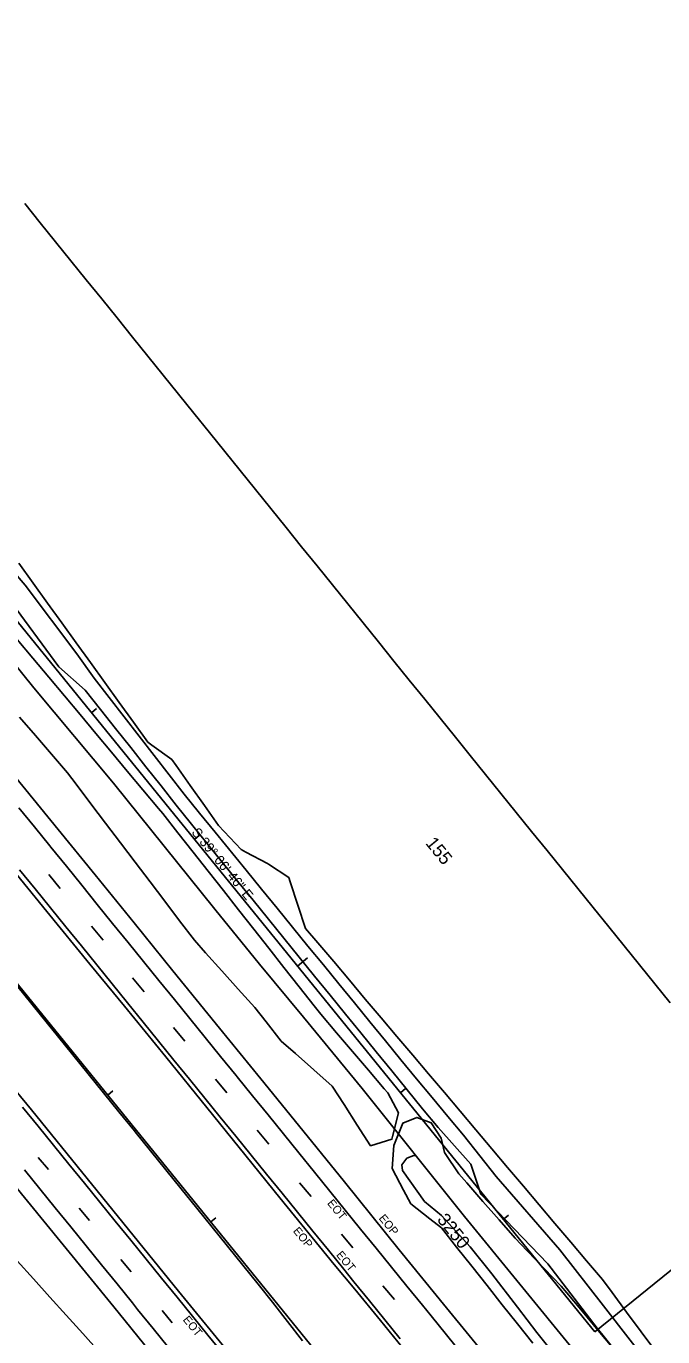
# Model space of a CAD drawing. Extents: x 2132221 to 2141942, y 535736 to 547298.
# Drawn here: x 2140690 to 2141080, y 537259 to 538062 of the extents above; entities that cross this region are included whole.
import ezdxf

# ---------------------------------------------------------------- set-up
doc = ezdxf.new("R2010")
doc.units = 0
for name, color, linetype in [('RD_EX_Driveway', 7, 'Continuous'), ('RD_EX_Fence_Other', 7, 'Continuous'), ('RD_EX_GuardRail', 7, 'Continuous'), ('RD_EX_Misc', 7, 'Continuous'), ('RD_EX_Misc_txCode', 7, 'Continuous'), ('RD_EX_Road', 7, 'Continuous'), ('RD_EX_Road_txCode', 7, 'Continuous'), ('RD_EX_VEG', 7, 'Continuous'), ('RD_HC_Cl', 7, 'Continuous'), ('RD_HC_Data', 7, 'Continuous'), ('RD_HC_Data_Tic', 7, 'Continuous'), ('RD_HC_TX_Sta50', 7, 'Continuous'), ('TOPO_E_TLIML-Line', 7, 'Continuous')]:
    doc.layers.add(name, color=color, linetype=linetype)

msp = doc.modelspace()

# ---------------------------------------------------------------- linework, layer by layer
at = {"layer": 'RD_EX_Driveway'}
for points in [[(2140458.06, 537995.95), (2140488.23, 537958.18), (2140519.81, 537918.83), (2140552.04, 537879.57), (2140579.22, 537846.81), (2140616.97, 537801.32), (2140652.79, 537761.62), (2140689.12, 537719.55), (2140720.75, 537677.36)], [(2140445.93, 537986.7), (2140475.53, 537947), (2140505.71, 537909.4), (2140538.89, 537870.87), (2140567.54, 537839.33), (2140606.35, 537793.62), (2140644.19, 537750.74), (2140678.5, 537711.95), (2140709.72, 537669.37)], [(2140977.54, 537357.23), (2140957.71, 537382.64), (2140948.07, 537394.14), (2140938.43, 537405.63), (2140928.8, 537417.13), (2140919.31, 537428.75), (2140909.82, 537440.36), (2140900.33, 537451.98), (2140890.84, 537463.6), (2140881.35, 537475.21), (2140871.86, 537486.83), (2140862.37, 537498.44), (2140852.88, 537510.06), (2140843.39, 537521.68), (2140833.89, 537533.29), (2140824.4, 537544.91), (2140805.42, 537568.14), (2140795.93, 537579.75), (2140786.57, 537591.47), (2140777.37, 537603.32), (2140768.17, 537615.17), (2140758.97, 537627.01), (2140749.77, 537638.86), (2140740.57, 537650.71), (2140731.37, 537662.55), (2140720.75, 537677.36)], [(2140709.72, 537669.37), (2140725.92, 537655.13), (2140735.22, 537643.4), (2140744.52, 537631.67), (2140753.81, 537619.94), (2140763.11, 537608.21), (2140772.41, 537596.48), (2140781.71, 537584.76), (2140791.01, 537573.03), (2140800.36, 537561.34), (2140809.8, 537549.73), (2140819.25, 537538.11), (2140828.69, 537526.5), (2140838.13, 537514.88), (2140847.57, 537503.27), (2140857.01, 537491.65), (2140866.45, 537480.04), (2140875.89, 537468.42), (2140885.33, 537456.81), (2140894.77, 537445.19), (2140904.21, 537433.58), (2140913.66, 537421.97), (2140923.1, 537410.35), (2140932.54, 537398.74), (2140942.15, 537387.27), (2140952.1, 537376.08), (2140962.04, 537364.9), (2140968.17, 537346.4)], [(2141235.1, 537045.22), (2141203.33, 537081.96), (2141160.78, 537134.96), (2141131.51, 537168.48), (2141076.12, 537236), (2141043.49, 537278.05), (2141016.72, 537312.47), (2140977.54, 537357.23)], [(2141223.68, 537037.44), (2141193.92, 537077.41), (2141159.91, 537117.65), (2141123.43, 537161.88), (2141072.58, 537223.3), (2141039.55, 537264.43), (2141009.36, 537303.88), (2140968.17, 537346.4)]]:
    msp.add_lwpolyline(points, dxfattribs=at)
at = {"layer": 'RD_EX_Fence_Other'}
msp.add_line((2140743.23, 537598.21), (2140694.45, 537656.5), dxfattribs=at)
for points in [[(2140437.03, 537975.97), (2140466.04, 537939.25), (2140495.76, 537901.58), (2140526.85, 537862.32), (2140555.79, 537827.47), (2140590, 537783.88), (2140627.49, 537738.23), (2140659.68, 537699.4), (2140694.45, 537656.5)], [(2140743.23, 537598.21), (2140774.22, 537559.63), (2140805.23, 537521.1), (2140832.75, 537487.27), (2140859.59, 537454.89), (2140895.5, 537411.2), (2140958.23, 537332.71), (2141227.49, 537003.41)]]:
    msp.add_lwpolyline(points, dxfattribs=at)
at = {"layer": 'RD_EX_GuardRail'}
msp.add_lwpolyline([(2140859.06, 537256.67), (2140849.83, 537268.49), (2140840.59, 537280.31), (2140831.95, 537291.37), (2140822.52, 537303.03), (2140813.08, 537314.69), (2140803.64, 537326.34), (2140794.2, 537338), (2140784.77, 537349.66), (2140775.33, 537361.32), (2140765.89, 537372.98), (2140756.46, 537384.64), (2140756.03, 537385.17), (2140746.59, 537396.83), (2140737.16, 537408.48), (2140727.72, 537420.14), (2140718.28, 537431.8), (2140708.85, 537443.46), (2140702.8, 537450.93), (2140693.37, 537462.59), (2140683.93, 537474.25)], dxfattribs=at)
at = {"layer": 'RD_EX_Misc'}
for p, q in [((2140703.53, 537542.15), (2140710.55, 537533.71)), ((2140729.82, 537510.53), (2140736.83, 537502.08)), ((2140754.96, 537478.9), (2140761.98, 537470.45)), ((2140779.93, 537448.53), (2140786.95, 537440.08)), ((2140805.67, 537416.91), (2140812.69, 537408.46)), ((2140831.3, 537385.64), (2140838.31, 537377.19)), ((2140697.06, 537369.03), (2140703.35, 537361.51)), ((2140857.23, 537353.42), (2140864.25, 537344.97)), ((2140722.26, 537337.95), (2140728.56, 537330.42)), ((2140882.86, 537322.04), (2140889.87, 537313.59)), ((2140747.77, 537306.44), (2140754.06, 537298.91)), ((2140908.3, 537290.35), (2140915.32, 537281.9)), ((2140772.95, 537275.19), (2140779.24, 537267.66))]:
    msp.add_line(p, q, dxfattribs=at)
for points in [[(2140685.31, 537583.05), (2140694.76, 537571.4), (2140704.22, 537559.75), (2140704.9, 537558.91), (2140714.35, 537547.26), (2140723.8, 537535.62), (2140733.25, 537523.97), (2140742.7, 537512.32), (2140752.15, 537500.67), (2140761.61, 537489.02), (2140771.06, 537477.38), (2140780.51, 537465.73), (2140789.96, 537454.08), (2140799.41, 537442.43), (2140808.86, 537430.79), (2140818.32, 537419.14), (2140819, 537418.29), (2140828.45, 537406.64), (2140837.91, 537395), (2140847.36, 537383.35), (2140856.81, 537371.7), (2140866.26, 537360.05), (2140875.71, 537348.41), (2140885.16, 537336.76), (2140894.61, 537325.11), (2140904.07, 537313.46), (2140913.52, 537301.81), (2140922.97, 537290.17), (2140932.42, 537278.52), (2140937.74, 537271.96), (2140947.19, 537260.32), (2140956.64, 537248.67)], [(2140685.7, 537545.06), (2140695.16, 537533.42), (2140704.61, 537521.77), (2140714.07, 537510.13), (2140723.53, 537498.49), (2140732.98, 537486.84), (2140742.44, 537475.2), (2140751.9, 537463.56), (2140761.36, 537451.91), (2140770.81, 537440.27), (2140780.27, 537428.63), (2140789.73, 537416.98), (2140799.18, 537405.34), (2140808.64, 537393.7), (2140818.1, 537382.05), (2140827.55, 537370.41), (2140837.01, 537358.77), (2140846.47, 537347.12), (2140855.93, 537335.48), (2140865.38, 537323.84), (2140874.84, 537312.19), (2140884.3, 537300.55), (2140890.55, 537292.86), (2140900, 537281.21), (2140909.46, 537269.57), (2140918.92, 537257.93)], [(2140687.55, 537399.83), (2140697.01, 537388.19), (2140706.47, 537376.55), (2140715.93, 537364.91), (2140725.39, 537353.27), (2140734.85, 537341.63), (2140744.31, 537329.99), (2140753.77, 537318.35), (2140763.23, 537306.71), (2140772.69, 537295.07), (2140782.15, 537283.43), (2140791.62, 537271.79), (2140801.08, 537260.15), (2140810.54, 537248.51)], [(2140776.94, 537252.61), (2140767.49, 537264.26), (2140758.03, 537275.9), (2140754.84, 537279.84), (2140745.38, 537291.49), (2140735.93, 537303.13), (2140726.47, 537314.78), (2140717.02, 537326.42), (2140707.57, 537338.07), (2140698.11, 537349.72), (2140688.66, 537361.36)]]:
    msp.add_lwpolyline(points, dxfattribs=at)
at = {"layer": 'RD_EX_Road'}
for points in [[(2140434.36, 537908.22), (2140460.47, 537876.18), (2140492.53, 537836.57), (2140520.2, 537802.5), (2140543.28, 537774.11), (2140569.92, 537741.29), (2140598.99, 537705.58), (2140635.15, 537660.72), (2140659.49, 537631.01), (2140683.25, 537601.85), (2140709.35, 537569.9), (2140732.09, 537542.02), (2140755.87, 537512.58), (2140779.68, 537483.3), (2140808.24, 537448.04), (2140833.52, 537417.03), (2140853.95, 537391.97), (2140884.7, 537353.95), (2140918.19, 537312.33)], [(2140401.79, 537889.76), (2140419.1, 537868.31), (2140440.28, 537842.06), (2140457.07, 537821.41), (2140479.63, 537793.5), (2140497.07, 537772.06), (2140528.29, 537733.78), (2140556.9, 537698.73), (2140580.71, 537669.45), (2140604.99, 537639.72), (2140623.48, 537616.74), (2140644.19, 537591.33), (2140661.9, 537569.77), (2140683.67, 537542.61), (2140702.49, 537519.59), (2140728.69, 537487.42), (2140749.87, 537461.7), (2140775.36, 537430.65), (2140800.43, 537399.52), (2140820.18, 537375.08), (2140845.19, 537344.29), (2140878.48, 537303.34)], [(2140331.4, 537842.81), (2140358.28, 537809.38), (2140388.82, 537771.67), (2140421.69, 537731.51), (2140479.51, 537660.25), (2140507.86, 537625.51), (2140538.58, 537587.96), (2140567.51, 537552.3), (2140601.53, 537510.68), (2140627.83, 537478.02), (2140656.06, 537443.32), (2140673.61, 537421.48), (2140693.03, 537398.17), (2140727.01, 537356.12), (2140758.56, 537317.28), (2140783, 537287.03), (2140817.12, 537245.45)], [(2140308.18, 537812.91), (2140330.69, 537785.06), (2140361.03, 537747.33), (2140386.29, 537716.18), (2140410.14, 537687.23), (2140429.5, 537663.09), (2140452.46, 537634.85), (2140479.43, 537601.73), (2140503.83, 537571.58), (2140530.32, 537539.38), (2140563.72, 537498.51), (2140596.15, 537458.64), (2140622.21, 537426.62), (2140652.24, 537389.59), (2140680.61, 537354.53), (2140712.38, 537315.48), (2140743.36, 537277.44), (2140765.02, 537250.67), (2140795.61, 537213.06)], [(2140918.19, 537312.33), (2140947.17, 537276.89), (2140973.09, 537245.24), (2141002.07, 537209.14), (2141026.69, 537178.71), (2141053.16, 537146.28), (2141085.78, 537106.42), (2141109.74, 537077.06), (2141135.97, 537044.44), (2141159.17, 537015.74), (2141186.81, 536981.82), (2141217.74, 536943.28), (2141243.15, 536912.57), (2141271.49, 536877.74), (2141303.6, 536838.39), (2141327.39, 536808.98), (2141353.08, 536777.18), (2141379.52, 536744.78), (2141400.21, 536719.53)], [(2140929.03, 537240.97), (2140920.01, 537252.67), (2140906.69, 537269.2), (2140891.07, 537288.23), (2140878.48, 537303.34)]]:
    msp.add_lwpolyline(points, dxfattribs=at)
at = {"layer": 'RD_EX_VEG'}
for points in [[(2141075.44, 537250.04), (2141066.5, 537262.08), (2141057.56, 537274.13), (2141048.62, 537286.17), (2141042.71, 537294.14), (2141033.03, 537305.59), (2141023.35, 537317.05), (2141013.67, 537328.51), (2141003.99, 537339.96), (2140994.31, 537351.42), (2140984.62, 537362.88), (2140974.94, 537374.34), (2140965.26, 537385.79), (2140955.58, 537397.25), (2140945.9, 537408.71), (2140936.22, 537420.17), (2140926.54, 537431.62), (2140916.85, 537443.08), (2140907.17, 537454.54), (2140897.49, 537465.99), (2140887.81, 537477.45), (2140878.13, 537488.91), (2140868.45, 537500.37), (2140860.92, 537509.27), (2140856.22, 537523.52), (2140851.52, 537537.76), (2140850.67, 537540.32), (2140838.17, 537548.61), (2140837.55, 537549.02), (2140824.29, 537556.03), (2140821.37, 537557.58), (2140811.11, 537568.52), (2140807.63, 537572.23), (2140798.94, 537584.46), (2140790.25, 537596.68), (2140781.55, 537608.91), (2140778.88, 537612.67), (2140766.75, 537621.5), (2140764.21, 537623.35), (2140755.44, 537635.52), (2140746.67, 537647.68), (2140737.89, 537659.85), (2140729.12, 537672.02), (2140720.35, 537684.18), (2140711.57, 537696.35), (2140702.8, 537708.52), (2140694.03, 537720.68), (2140685.25, 537732.85)], [(2140684.27, 537686.18), (2140693.89, 537674.67), (2140703.52, 537663.17), (2140713.14, 537651.66), (2140722.76, 537640.15), (2140732.38, 537628.65), (2140742.01, 537617.14), (2140751.63, 537605.63), (2140761.25, 537594.13), (2140770.87, 537582.62), (2140773.42, 537579.57), (2140782.7, 537567.79), (2140791.98, 537556.01), (2140801.26, 537544.22), (2140810.55, 537532.44), (2140819.83, 537520.65), (2140829.11, 537508.87), (2140838.39, 537497.09), (2140847.67, 537485.3), (2140856.95, 537473.52), (2140866.24, 537461.74), (2140870.19, 537456.72), (2140879.91, 537445.29), (2140889.63, 537433.87), (2140899.35, 537422.44), (2140909.07, 537411.02), (2140911.21, 537408.5), (2140917.77, 537396.29), (2140914.2, 537381.72), (2140913.8, 537380.1), (2140900.68, 537376.13), (2140892.55, 537388.74), (2140884.43, 537401.35), (2140877.17, 537412.62), (2140865.95, 537422.58), (2140854.74, 537432.54), (2140846.04, 537440.26), (2140836.72, 537452.02), (2140829.71, 537460.88), (2140819.69, 537472.04), (2140809.67, 537483.2), (2140799.65, 537494.37), (2140792.81, 537501.99), (2140783.74, 537513.94), (2140774.67, 537525.89), (2140765.61, 537537.84), (2140756.54, 537549.79), (2140747.47, 537561.73), (2140738.4, 537573.68), (2140729.33, 537585.63), (2140720.27, 537597.58), (2140714.96, 537604.57), (2140705.17, 537615.93), (2140695.38, 537627.29), (2140685.58, 537638.65)], [(2141049.69, 537251.55), (2141040.09, 537263.08), (2141030.49, 537274.61), (2141020.89, 537286.13), (2141017.52, 537290.18), (2141007.12, 537300.99), (2140996.71, 537311.79), (2140989.29, 537319.5), (2140979.41, 537330.79), (2140969.53, 537342.08), (2140959.65, 537353.37), (2140954.81, 537358.9), (2140946.48, 537371.37), (2140946.01, 537372.07), (2140944.04, 537380.85), (2140937.84, 537390.18), (2140929.12, 537393.5), (2140920.49, 537390.01), (2140914.99, 537376.31), (2140913.86, 537362.17), (2140920.89, 537348.92), (2140925.29, 537340.62), (2140937.07, 537331.34), (2140944.12, 537325.79), (2140953.44, 537314.03), (2140962.76, 537302.28), (2140972.08, 537290.52), (2140981.39, 537278.77), (2140990.71, 537267.01), (2141000.03, 537255.26)], [(2141015.05, 537246.24), (2141002.46, 537261.67), (2140990.75, 537277.29), (2140974.92, 537297.76), (2140961.66, 537314.22), (2140944.15, 537333.32), (2140933.76, 537341.98), (2140920.27, 537360.87), (2140919.86, 537364.37), (2140922.97, 537368.49), (2140927.27, 537370.07), (2140927.91, 537369.92)], [(2140684.18, 537305.68), (2140694.22, 537294.54), (2140704.27, 537283.4), (2140714.32, 537272.27), (2140724.36, 537261.13), (2140734.41, 537249.99)]]:
    msp.add_lwpolyline(points, dxfattribs=at)
at = {"layer": 'RD_HC_Cl'}
for p, q in [((2136971.61, 542041.65), (2141699.63, 536226.46)), ((2140578.77, 537826.98), (2141038.08, 537262.06))]:
    msp.add_line(p, q, dxfattribs=at)
at = {"layer": 'RD_HC_Data'}
msp.add_line((2141038.08, 537262.06), (2141139.48, 537344.5), dxfattribs=at)
at = {"layer": 'RD_HC_Data_Tic'}
for p, q in [((2140729.69, 537641.36), (2140732.79, 537643.88)), ((2140792.77, 537563.77), (2140795.88, 537566.29)), ((2140855.86, 537486.18), (2140862.07, 537491.23)), ((2140739.69, 537407.13), (2140742.79, 537409.66)), ((2140918.94, 537408.59), (2140922.05, 537411.11)), ((2140802.78, 537329.54), (2140805.88, 537332.07)), ((2140982.03, 537331), (2140985.13, 537333.52))]:
    msp.add_line(p, q, dxfattribs=at)
at = {"layer": 'TOPO_E_TLIML-Line'}
msp.add_lwpolyline([(2141084.32, 537463.66), (2141074.88, 537475.32), (2141065.45, 537486.98), (2141056.01, 537498.64), (2141046.57, 537510.3), (2141037.13, 537521.96), (2141027.7, 537533.62), (2141018.26, 537545.28), (2141008.82, 537556.94), (2140999.38, 537568.6), (2140989.95, 537580.26), (2140980.51, 537591.92), (2140971.07, 537603.57), (2140961.64, 537615.23), (2140952.69, 537626.28), (2140943.27, 537637.96), (2140933.85, 537649.63), (2140924.43, 537661.3), (2140915.01, 537672.97), (2140905.59, 537684.65), (2140896.17, 537696.32), (2140886.75, 537707.99), (2140877.33, 537719.67), (2140867.9, 537731.34), (2140858.48, 537743.01), (2140849.06, 537754.68), (2140839.64, 537766.36), (2140830.22, 537778.03), (2140820.8, 537789.7), (2140811.38, 537801.37), (2140801.96, 537813.05), (2140792.54, 537824.72), (2140783.12, 537836.39), (2140773.7, 537848.06), (2140764.28, 537859.74), (2140754.86, 537871.41), (2140745.43, 537883.08), (2140736.01, 537894.75), (2140726.59, 537906.43), (2140717.17, 537918.1), (2140707.75, 537929.77), (2140698.33, 537941.44), (2140688.91, 537953.12)], dxfattribs=at)

# ---------------------------------------------------------------- texts
at = {"layer": 'RD_EX_Misc_txCode'}
for p in [(2140873.85, 537340.79), (2140879.34, 537309.15), (2140785.45, 537269.45)]:
    msp.add_text('EOT', height=5, rotation=309.5103, dxfattribs=at).set_placement(p)
at = {"layer": 'RD_EX_Road_txCode'}
for p in [(2140905.42, 537331.6), (2140852.91, 537323.8)]:
    msp.add_text('EOP', height=5, rotation=309.5103, dxfattribs=at).set_placement(p)
at = {"layer": 'RD_HC_Data'}
msp.add_text('S 39%%d 06\' 46" E', height=6, rotation=309.11274, dxfattribs=at).set_placement((2140790.68, 537567.93))
at = {"layer": 'RD_HC_TX_Sta50'}
for s, p in [('155', (2140933.99, 537561.28)), ('3250', (2140941.04, 537330.68))]:
    msp.add_text(s, height=8, rotation=309.11274, dxfattribs=at).set_placement(p)

doc.saveas('drawing.dxf')
